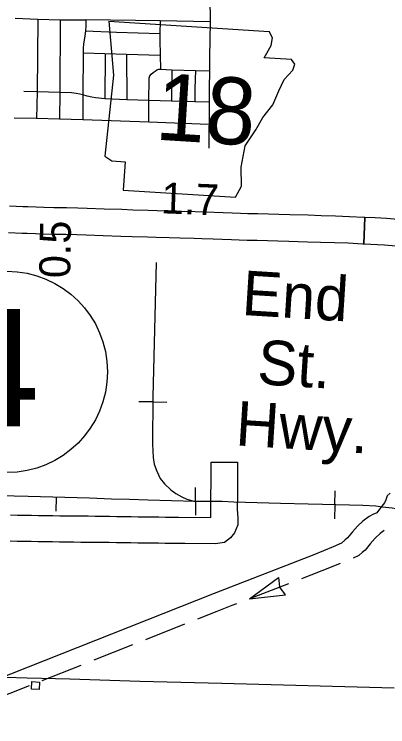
# Model space of a CAD drawing. Extents: x 1366406 to 1373462, y 376856 to 381998.
# Drawn here: x 1369377 to 1369434.3, y 379865.5 to 379974.8 of the extents above; entities that cross this region are included whole.
import ezdxf

# ---------------------------------------------------------------- set-up
doc = ezdxf.new("R2010")
doc.units = 0
for name, color, linetype in [('10', 7, 'Continuous'), ('21', 7, 'Continuous'), ('33', 7, 'Continuous'), ('40', 7, 'Continuous'), ('41', 7, 'Continuous'), ('43', 7, 'Continuous'), ('48', 7, 'Continuous'), ('56', 7, 'Continuous'), ('R_Draft', 7, 'Continuous')]:
    doc.layers.add(name, color=color, linetype=linetype)

msp = doc.modelspace()

# ---------------------------------------------------------------- linework, layer by layer
at = {"layer": '10'}
for points in [[(1369430.64, 379939.6), (1369430.77, 379943.65), (1369430.63, 379943.65), (1369428.41, 379943.77), (1369426.25, 379943.85), (1369424.07, 379943.91), (1369422.09, 379943.98), (1369419.24, 379944.03), (1369417.57, 379944.1), (1369415.98, 379944.15), (1369414.33, 379944.2), (1369412.83, 379944.23), (1369411.67, 379944.28), (1369410.41, 379944.33), (1369409.02, 379944.36), (1369407.65, 379944.41), (1369405.91, 379944.47), (1369404.72, 379944.51), (1369402.51, 379944.56), (1369400.88, 379944.61), (1369398.91, 379944.68), (1369397.53, 379944.73), (1369395.17, 379944.78), (1369393.48, 379944.85), (1369390.78, 379944.91), (1369388.18, 379945.02), (1369386.72, 379945.06), (1369385.02, 379945.11), (1369383.07, 379945.15), (1369381.5, 379945.2), (1369380.36, 379945.24), (1369379.06, 379945.28), (1369378.31, 379945.29), (1369376.25, 379945.37)], [(1369443.79, 379942.71), (1369442.61, 379942.78), (1369441.49, 379942.88), (1369440.51, 379942.96), (1369439.47, 379943.05), (1369437.6, 379943.22), (1369435.86, 379943.34), (1369434.1, 379943.49), (1369432.36, 379943.6), (1369430.77, 379943.65), (1369430.64, 379939.6), (1369433.8, 379939.45), (1369435.54, 379939.3), (1369437.27, 379939.18), (1369439.1, 379939.01)], [(1369376.08, 379941.32), (1369378.2, 379941.24), (1369378.95, 379941.23), (1369380.22, 379941.19), (1369381.37, 379941.15), (1369382.97, 379941.1), (1369384.92, 379941.07), (1369386.6, 379941.01), (1369388.04, 379940.97), (1369390.64, 379940.86), (1369393.34, 379940.8), (1369395.05, 379940.73), (1369397.42, 379940.68), (1369398.76, 379940.63), (1369400.75, 379940.56), (1369402.4, 379940.51), (1369404.6, 379940.46), (1369405.78, 379940.42), (1369407.51, 379940.36), (1369408.89, 379940.31), (1369410.29, 379940.28), (1369411.5, 379940.24), (1369412.7, 379940.18), (1369414.24, 379940.15), (1369415.86, 379940.1), (1369417.43, 379940.06), (1369419.11, 379939.99), (1369421.97, 379939.93), (1369423.95, 379939.86), (1369426.13, 379939.8), (1369428.23, 379939.73), (1369430.46, 379939.61), (1369430.64, 379939.6)], [(1369407.12, 379897.6), (1369407.14, 379899.32), (1369407.15, 379899.6), (1369407.15, 379899.89), (1369407.16, 379900.16), (1369407.16, 379900.48), (1369407.16, 379900.84), (1369407.16, 379901.25), (1369407.16, 379901.71), (1369407.17, 379902.17), (1369407.17, 379902.66), (1369407.17, 379903.19), (1369407.18, 379903.71), (1369407.17, 379904.24), (1369407.17, 379904.78), (1369407.17, 379905.27), (1369407.17, 379905.66), (1369407.17, 379905.92), (1369407.18, 379906.11), (1369411.23, 379906.1)], [(1369411.23, 379906.1), (1369411.22, 379905.9), (1369411.22, 379905.62), (1369411.22, 379905.25), (1369411.22, 379904.79), (1369411.22, 379904.27), (1369411.23, 379903.72), (1369411.22, 379903.16), (1369411.22, 379902.64), (1369411.22, 379902.14), (1369411.21, 379901.67), (1369411.21, 379901.24), (1369411.21, 379900.83), (1369411.21, 379900.46), (1369411.21, 379900.12), (1369411.2, 379899.8), (1369411.19, 379899.53), (1369411.19, 379899.27), (1369411.19, 379898.97), (1369411.21, 379898.13), (1369411.26, 379897.63), (1369411.26, 379896.45), (1369410.78, 379895.24), (1369410.17, 379894.45), (1369409.22, 379893.75), (1369407.82, 379893.54)], [(1369376.41, 379897.99), (1369377.5, 379897.97), (1369378.57, 379897.96), (1369379.65, 379897.94), (1369380.72, 379897.92), (1369381.8, 379897.9), (1369382.88, 379897.89), (1369383.96, 379897.87), (1369385.04, 379897.86), (1369386.12, 379897.84), (1369387.21, 379897.83), (1369388.3, 379897.83), (1369389.39, 379897.82), (1369390.5, 379897.8), (1369391.6, 379897.79), (1369392.71, 379897.77), (1369393.81, 379897.75), (1369394.9, 379897.74), (1369395.98, 379897.72), (1369397.05, 379897.71), (1369398.11, 379897.69), (1369399.16, 379897.68), (1369400.19, 379897.66), (1369401.2, 379897.65), (1369402.19, 379897.64), (1369407.12, 379897.6)], [(1369407.82, 379893.54), (1369403.13, 379893.58), (1369402.15, 379893.59), (1369401.16, 379893.6), (1369400.14, 379893.61), (1369399.1, 379893.63), (1369398.05, 379893.64), (1369396.99, 379893.66), (1369395.93, 379893.67), (1369394.85, 379893.69), (1369393.75, 379893.7), (1369392.65, 379893.72), (1369391.54, 379893.74), (1369390.44, 379893.75), (1369389.35, 379893.77), (1369388.27, 379893.78), (1369387.18, 379893.78), (1369386.08, 379893.79), (1369384.99, 379893.81), (1369383.91, 379893.82), (1369382.83, 379893.84), (1369381.75, 379893.85), (1369380.66, 379893.87), (1369379.58, 379893.89), (1369378.5, 379893.91), (1369377.44, 379893.92), (1369376.37, 379893.94)]]:
    msp.add_lwpolyline(points, dxfattribs=at)
at = {"layer": '21'}
for p, q in [((1369391.49, 379973.78), (1369392.2, 379965.49)), ((1369416.59, 379971.24), (1369416.08, 379972.22)), ((1369416.38, 379970.02), (1369416.59, 379971.24)), ((1369415.3, 379968.17), (1369416.38, 379970.02)), ((1369419.54, 379967.9), (1369415.3, 379968.17)), ((1369420.04, 379967.18), (1369419.54, 379967.9)), ((1369419.71, 379966.24), (1369420.04, 379967.18)), ((1369418.39, 379964.81), (1369419.71, 379966.24)), ((1369392.2, 379965.49), (1369390.88, 379953.08)), ((1369417.59, 379963.08), (1369418.39, 379964.81)), ((1369416.63, 379960.94), (1369417.59, 379963.08)), ((1369415.14, 379958.98), (1369416.63, 379960.94)), ((1369414.06, 379957.12), (1369415.14, 379958.98)), ((1369412.39, 379954.62), (1369414.06, 379957.12)), ((1369411.78, 379951.36), (1369412.39, 379954.62)), ((1369390.88, 379953.08), (1369391.93, 379952.33)), ((1369391.93, 379952.33), (1369393.98, 379952.2)), ((1369393.98, 379952.2), (1369393.71, 379947.83)), ((1369411.87, 379948.47), (1369411.78, 379951.36)), ((1369410.94, 379946.75), (1369411.87, 379948.47)), ((1369393.71, 379947.83), (1369410.94, 379946.75))]:
    msp.add_line(p, q, dxfattribs=at)
msp.add_lwpolyline([(1369391.49, 379973.78), (1369416.08, 379972.22)], dxfattribs=at)
at = {"layer": '33'}
for points in [[(1369406.65, 379979.04), (1369406.81, 379978.72), (1369406.92, 379978.42), (1369406.99, 379978.06), (1369407, 379977.44), (1369407.05, 379973.7)], [(1369377.12, 379974.25), (1369380.6, 379974.1), (1369384.05, 379974.01), (1369387.94, 379974.01)], [(1369380.6, 379974.1), (1369380.5, 379962.95), (1369380.42, 379958.84)], [(1369384.05, 379974.01), (1369383.99, 379962.85), (1369383.92, 379958.75)], [(1369387.94, 379974.01), (1369387.94, 379973.03), (1369387.89, 379972.28), (1369387.79, 379971.53), (1369387.61, 379970.23), (1369387.56, 379969.64), (1369387.55, 379968.9), (1369387.52, 379962.46), (1369387.52, 379958.68)], [(1369407.05, 379973.7), (1369399.39, 379973.81), (1369387.94, 379974.01)], [(1369399.39, 379973.81), (1369399.33, 379971.89), (1369399.34, 379970.92), (1369399.39, 379968.57), (1369399.41, 379966.43)], [(1369407.05, 379973.7), (1369406.94, 379968.23)], [(1369387.89, 379972.28), (1369392.69, 379972.1), (1369399.33, 379971.89)], [(1369387.55, 379968.9), (1369394.22, 379968.69), (1369399.39, 379968.57)], [(1369390.94, 379968.79), (1369390.87, 379961.86)], [(1369394.22, 379968.69), (1369394.26, 379961.73)], [(1369406.94, 379968.23), (1369406.9, 379961.34), (1369406.81, 379954.27)], [(1369397.64, 379958.29), (1369397.65, 379961.62), (1369397.67, 379964.76), (1369397.69, 379965.04), (1369397.77, 379965.4), (1369397.99, 379965.65), (1369398.31, 379965.92), (1369398.62, 379966.13), (1369398.88, 379966.3), (1369399.14, 379966.4), (1369399.41, 379966.43), (1369401.14, 379966.32), (1369404.81, 379966.22), (1369406.92, 379966.17)], [(1369401.14, 379966.32), (1369401.12, 379961.52)], [(1369404.81, 379966.22), (1369404.69, 379963.43), (1369404.71, 379961.41)], [(1369406.9, 379961.34), (1369404.71, 379961.41), (1369402.69, 379961.44), (1369401.12, 379961.52), (1369397.65, 379961.62), (1369394.26, 379961.73), (1369390.87, 379961.86), (1369389.97, 379961.95), (1369389.43, 379962.02), (1369388.9, 379962.11), (1369388.19, 379962.29), (1369387.52, 379962.46), (1369387.05, 379962.56), (1369386.5, 379962.67), (1369386.14, 379962.72), (1369385.78, 379962.78), (1369380.5, 379962.95), (1369378.43, 379963)], [(1369406.85, 379957.92), (1369397.64, 379958.29), (1369387.51, 379958.66), (1369383.92, 379958.75), (1369380.42, 379958.84), (1369376.99, 379958.9)]]:
    msp.add_lwpolyline(points, dxfattribs=at)
at = {"layer": '40'}
for p, q in [((1369398.25, 379915.34), (1369396.11, 379915.35)), ((1369398.25, 379915.34), (1369400.39, 379915.32)), ((1369404.79, 379900.07), (1369404.8, 379902.2)), ((1369426.16, 379899.55), (1369426.22, 379901.69)), ((1369383.41, 379900.69), (1369383.35, 379898.55)), ((1369404.79, 379900.07), (1369404.77, 379897.93)), ((1369426.16, 379899.55), (1369426.1, 379897.41))]:
    msp.add_line(p, q, dxfattribs=at)
for points in [[(1369398.73, 379936.72), (1369398.25, 379916.1), (1369398.2, 379908.83), (1369398.28, 379906.83), (1369398.43, 379905.79), (1369398.87, 379904.71), (1369399.39, 379903.57), (1369400.04, 379902.76), (1369401.02, 379901.83), (1369401.75, 379901.29), (1369402.67, 379900.79), (1369403.45, 379900.4), (1369404.72, 379900.07)], [(1369398.73, 379936.72), (1369398.25, 379916.1), (1369398.2, 379908.83), (1369398.28, 379906.83), (1369398.43, 379905.79), (1369398.87, 379904.71), (1369399.39, 379903.57), (1369400.04, 379902.76), (1369401.02, 379901.83), (1369401.75, 379901.29), (1369402.67, 379900.79), (1369403.45, 379900.4), (1369404.72, 379900.07)], [(1369379.12, 379900.81), (1369374.81, 379900.92), (1369370.87, 379901.06), (1369361.43, 379901.26), (1369355.04, 379901.5)], [(1369438.31, 379898.39), (1369437.28, 379898.55), (1369436.07, 379898.8), (1369434.95, 379899.01), (1369433.46, 379899.2), (1369432.48, 379899.31), (1369430.48, 379899.43), (1369424.27, 379899.61), (1369422.07, 379899.63), (1369417.84, 379899.76), (1369410.69, 379899.95), (1369408.88, 379900.04), (1369404.72, 379900.07), (1369397.48, 379900.24), (1369394.68, 379900.38), (1369391.91, 379900.42), (1369388.51, 379900.55), (1369379.12, 379900.81)], [(1369435.27, 379871.38), (1369408.84, 379872.09), (1369396.27, 379872.42), (1369385.51, 379872.78), (1369378.98, 379872.92), (1369375.64, 379873.02)]]:
    msp.add_lwpolyline(points, dxfattribs=at)
at = {"layer": '43'}
for p, q in [((1369413.05, 379885.12), (1369417.54, 379888.4)), ((1369417.54, 379888.4), (1369417.7, 379886.93)), ((1369418.58, 379885.71), (1369417.71, 379886.91)), ((1369413.05, 379885.12), (1369418.58, 379885.71))]:
    msp.add_line(p, q, dxfattribs=at)
for points in [[(1369434.66, 379901.35), (1369434.19, 379900.9), (1369434.01, 379900.32), (1369433.78, 379899.84), (1369433.16, 379899.07), (1369432.61, 379898.31), (1369431.98, 379898.05), (1369431.44, 379897.75), (1369430.46, 379897.03), (1369429.65, 379896.27), (1369428.9, 379895.42), (1369428.12, 379894.47), (1369427.7, 379894.1), (1369427.17, 379893.65), (1369425.93, 379893.07), (1369422.93, 379891.84), (1369407.66, 379885.94), (1369363.34, 379868.38), (1369360.15, 379865.84), (1369359.55, 379865.13)], [(1369433.72, 379895.59), (1369433.14, 379895.16), (1369432.33, 379894.4), (1369431.58, 379893.56), (1369430.8, 379892.6), (1369430.38, 379892.23), (1369429.85, 379891.78), (1369428.97, 379891.37)], [(1369427, 379890.54), (1369425.61, 379889.98), (1369421.03, 379888.2)], [(1369419.04, 379887.43), (1369413.05, 379885.12)], [(1369411.06, 379884.35), (1369410.34, 379884.08), (1369408.07, 379883.18)], [(1369408.07, 379883.18), (1369405.09, 379881.99)], [(1369403.1, 379881.21), (1369397.14, 379878.84)], [(1369395.15, 379878.05), (1369389.19, 379875.69)], [(1369387.2, 379874.9), (1369381.23, 379872.54)], [(1369379.25, 379871.75), (1369373.28, 379869.39)]]:
    msp.add_lwpolyline(points, dxfattribs=at)
at = {"layer": '56'}
msp.add_lwpolyline([(1369379.62, 379871.25), (1369379.69, 379872.42), (1369380.86, 379872.34), (1369380.79, 379871.18)], close=True, dxfattribs=at)
at = {"layer": 'R_Draft'}
msp.add_circle((1369375.84, 379919.94), 15.45, dxfattribs=at)

# ---------------------------------------------------------------- texts
at = {"layer": '21'}
msp.add_text('18', height=10.264, rotation=356.4139, dxfattribs=at).set_placement((1369398.47, 379955.61))
at = {"layer": '41'}
for s, p in [('End', (1369411.78, 379928.7)), ('St.', (1369414.15, 379918.08)), ('Hwy.', (1369410.83, 379908.68))]:
    msp.add_text(s, height=6.843, rotation=356.4139, dxfattribs=at).set_placement(p)
at = {"layer": '48'}
for s, rotation, p in [('1.7', 357.7166, (1369399.44, 379944.3)), ('0.5', 89.0752, (1369385.55, 379934.3))]:
    msp.add_text(s, height=4.752, rotation=rotation, dxfattribs=at).set_placement(p)
at = {"layer": 'R_Draft'}
msp.add_text('4', height=18, dxfattribs=at).set_placement((1369367.5, 379911.59))

doc.saveas('drawing.dxf')
